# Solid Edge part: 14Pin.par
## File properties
Author: conerly
Template: ansi part.par
Last saved by: jccrumbl
Revision: 24
Application: Solid Edge
Density: 0.0979772159 lbm/in^3
Accuracy: 0.990
Material: Aluminum, 1060
Face Style: Aluminum
Fill Style: ANSI38(Aluminum)
Virtual Style: Polished aluminum
Coef. of Thermal Exp: 2.3e-05
Thermal Conductivity: 221.0
Specific Heat: 920.0
Modulus of Elasticity: 68947570000.0
Poisson's Ratio: 0.33
Yield Stress: 27579028.0
Ultimate Stress: 68947570.0
Elongation: 0.0
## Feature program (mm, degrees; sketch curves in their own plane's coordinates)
sketch for "unnamed Protrusion 1" plane through (10.8687, 0, 10.8687) normal (0, -1, 0) x-axis (1, 0, 0)
  line (-26.3687, -16.8687) -> (4.6313, -16.8687)
  line (4.6313, -16.8687) -> (4.6313, -4.8687)
  line (4.6313, -4.8687) -> (-26.3687, -4.8687)
  line (-26.3687, -4.8687) -> (-26.3687, -16.8687)
  dimension (linear) = 4.6313
  dimension (linear) = 26.3687
extrude "unnamed Protrusion 1" add finite 6.35 along -normal
sketch for "unnamed Cutout 1" plane through (0, 0, 0) normal (0, -1, 0) x-axis (1, 0, 0)
  circle centre (-12.96, 3.46) radius 1.27
extrude "unnamed Cutout 1" cut through along -normal
pattern "unnamed Pattern 1" of "unnamed Cutout 1"
extrude "unnamed Cutout 2" cut through
extrude "unnamed Cutout 3" cut through
extrude "unnamed Cutout 4" cut through
extrude "unnamed Cutout 5" cut through
extrude "unnamed Cutout 6" cut through
extrude "unnamed Cutout 7" cut through
extrude "unnamed Cutout 8" cut through
extrude "unnamed Cutout 9" cut through
extrude "unnamed Cutout 10" cut through
extrude "unnamed Cutout 11" cut through
extrude "unnamed Cutout 12" cut through
extrude "unnamed Cutout 13" cut through
extrude "unnamed Cutout 14" cut through
sketch for "ExtrudedProtrusion_2" plane through (0, 0, 0) normal (0, -1, 0) x-axis (1, 0, 0)
  line (-15.5, 1.5473) -> (15.5, 1.5473)
  line (15.5, 1.5473) -> (15.5, -1.0137)
  line (15.5, -1.0137) -> (-15.5, -1.0137)
  line (-15.5, -1.0137) -> (-15.5, 1.5473)
extrude "ExtrudedProtrusion_2" add finite 1.524 along +normal
sketch for "unnamed Protrusion 2" plane through (0, 0, -3.5069) normal (0, -1, 0) x-axis (1, 0, 0)
  line (-15.5, 9.5069) -> (-15.5, -2.4931)
  line (-15.5, -2.4931) -> (-14.4057, -2.4931)
  line (-14.4057, -2.4931) -> (-14.4057, 9.5069)
  line (-14.4057, 9.5069) -> (-15.5, 9.5069)
extrude "unnamed Protrusion 2" add to key point along +normal
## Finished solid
Body 1: solid body, 26 faces, 58 edges, 20 vertices.
  Faces by surface: cylinder 14, plane 12
  Edges by curve: line 30, circle 28
Bounding box of the edges (mm): 31.000 x 7.874 x 12.000, from (-15.5, -1.524, -6) to (15.5, 6.35, 6).
Cylindrical faces by radius (mm): R1.27 x14
Planar faces by outward normal: +x 3, +y 1, +z 2, -x 1, -y 3, -z 2
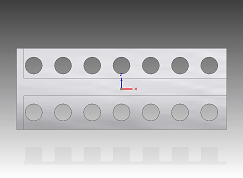
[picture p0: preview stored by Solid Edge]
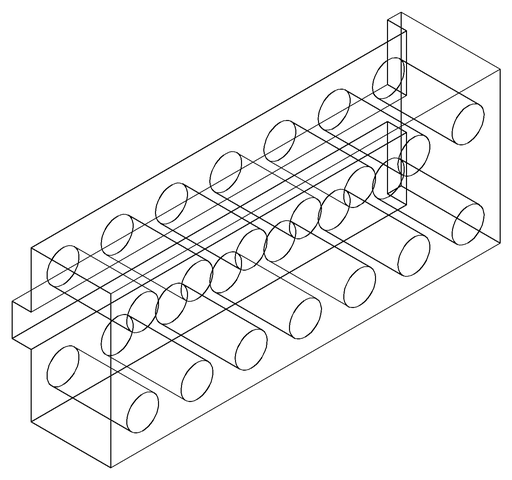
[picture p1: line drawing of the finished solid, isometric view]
